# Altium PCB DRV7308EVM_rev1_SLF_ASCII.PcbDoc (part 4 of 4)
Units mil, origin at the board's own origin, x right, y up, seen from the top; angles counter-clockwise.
Board outline 6187 x 6000 mil, 4 copper layers (Top Layer, Ground, Power, Bottom Layer), stack 61.2 mil thick; 306 components, 128 nets, 676 pads, 1026 vias.
Unrouted connection lines stored in the file: 208.
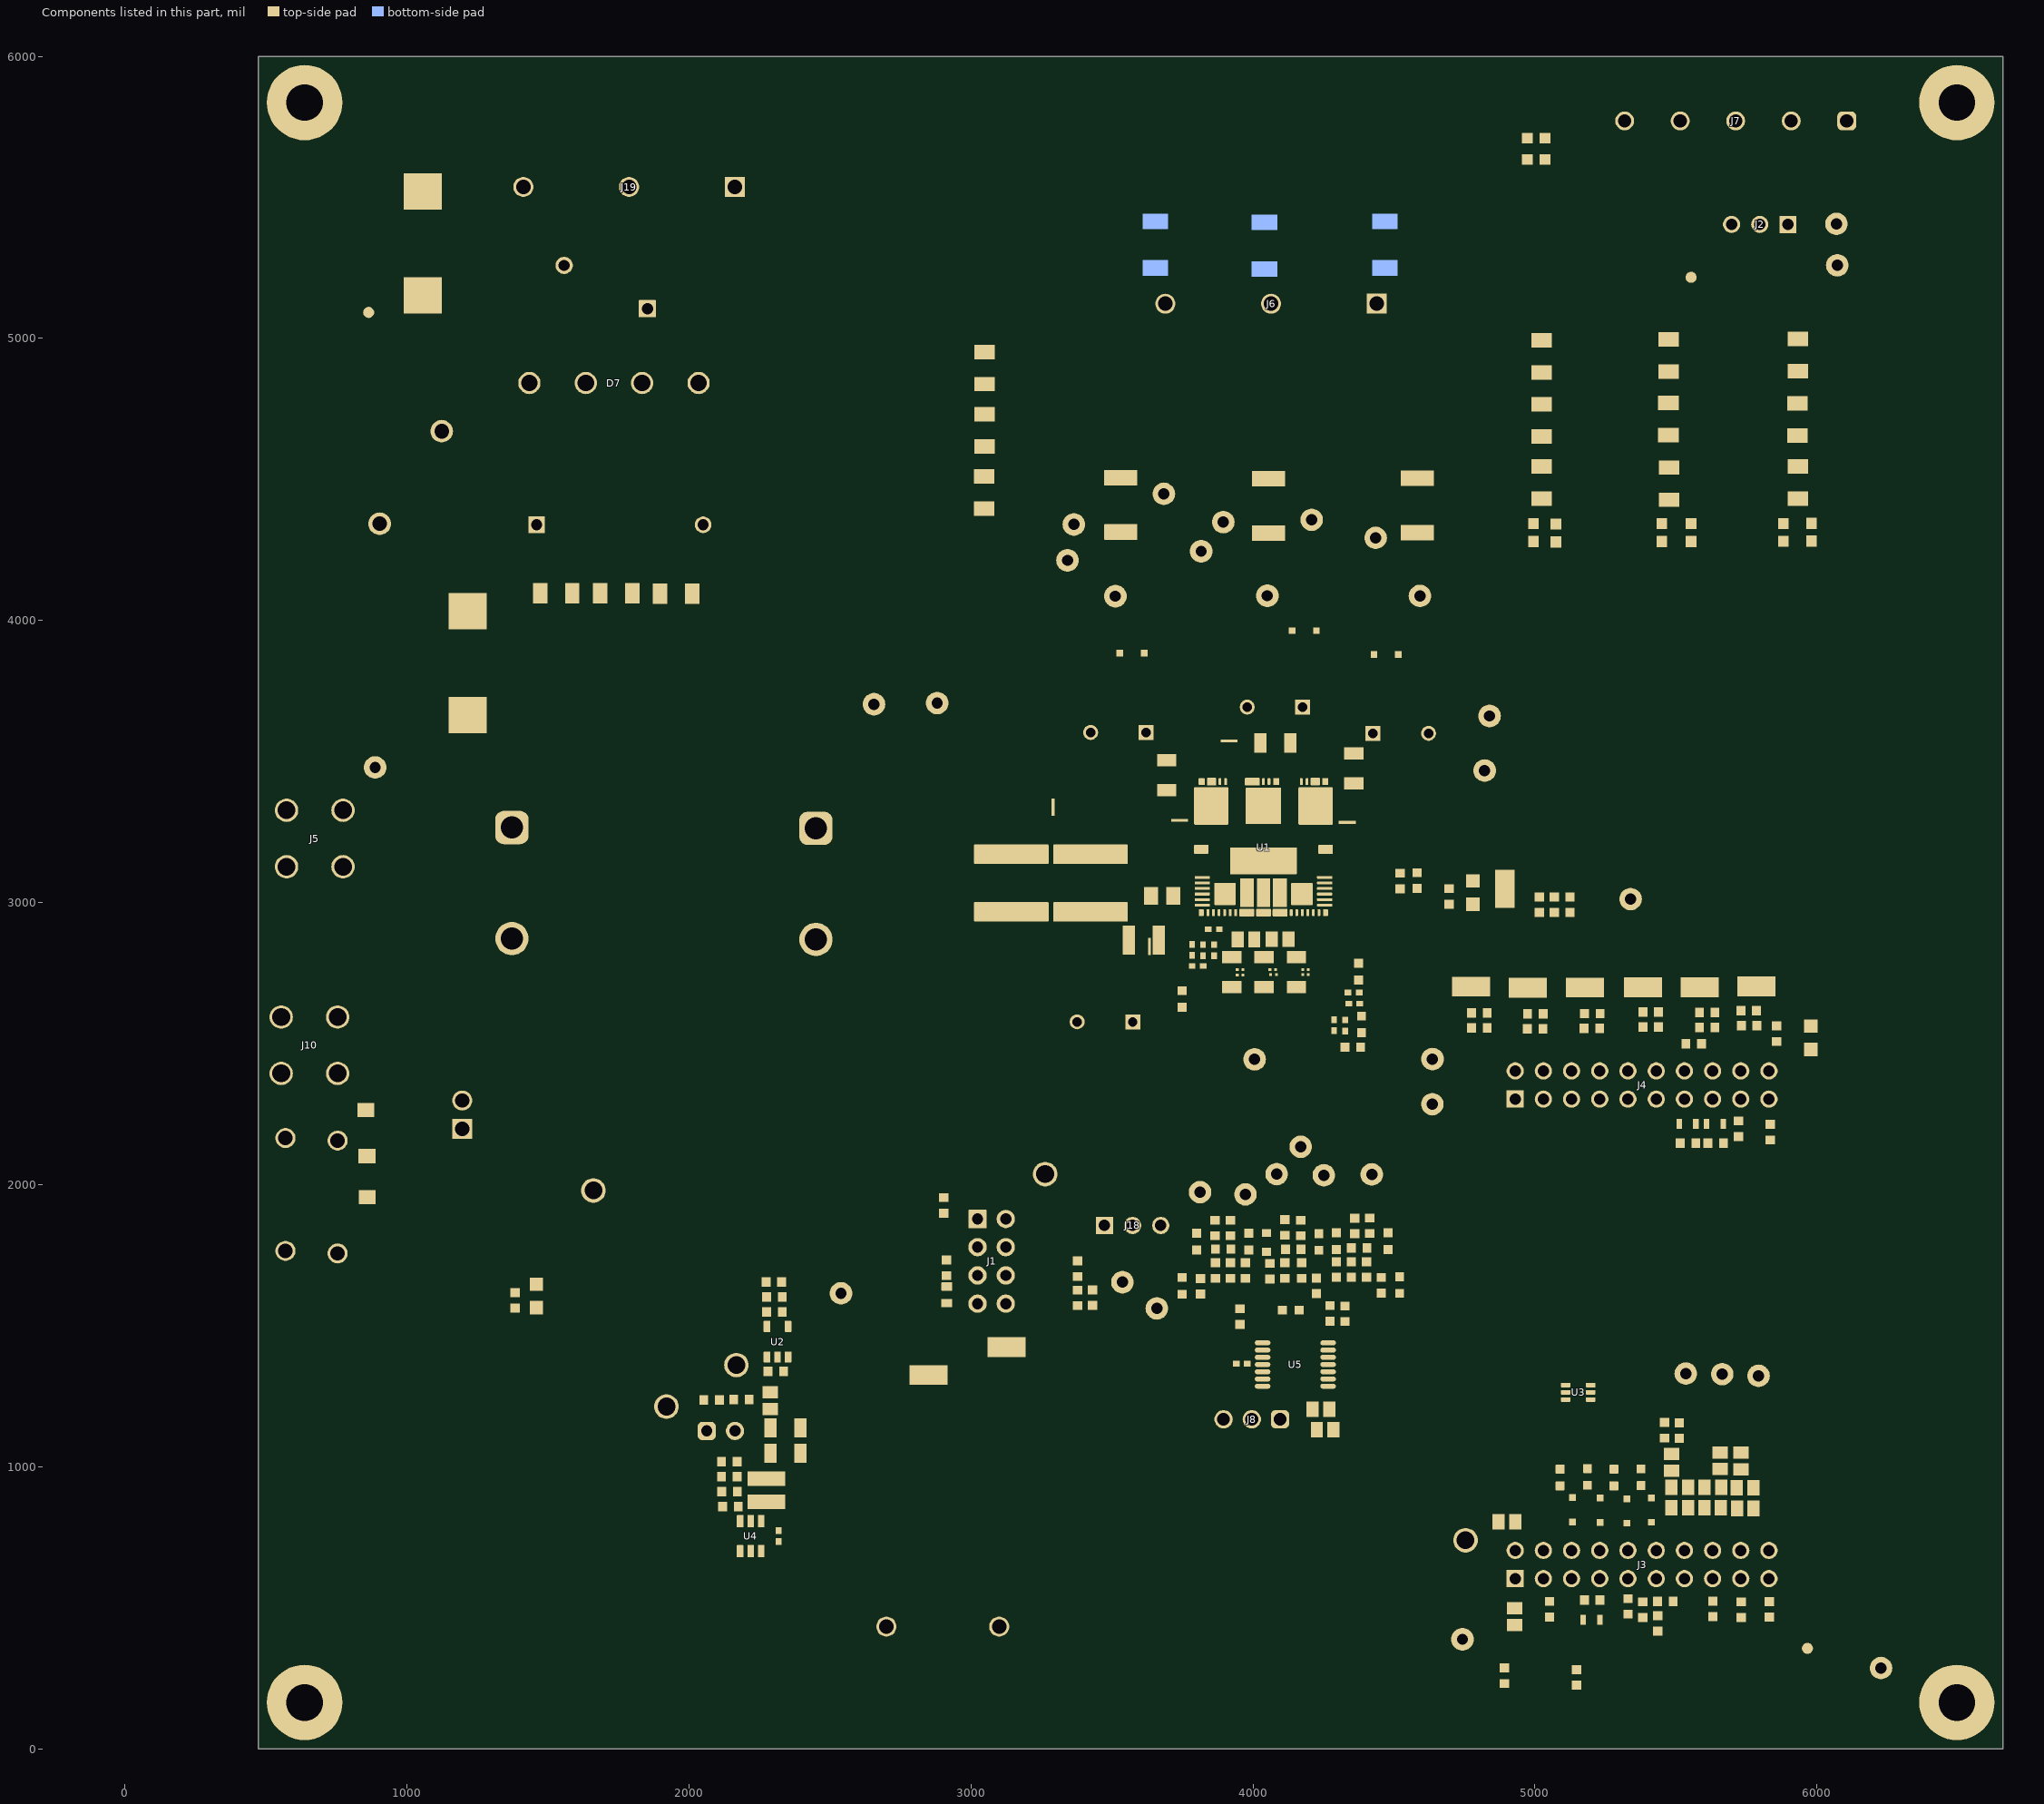
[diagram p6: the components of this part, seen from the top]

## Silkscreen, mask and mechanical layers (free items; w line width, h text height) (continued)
M2 Board Dimensions:
  rectangle: 283.77,-637.3 408.77,-512.3
  rectangle: 408.77,-762.3 783.77,-637.3
  lines w7: 283.77,-637.3 1283.77,-637.3 ; 408.77,-762.3 408.77,-512.3 ; 533.77,-762.3 533.77,-512.3 ; 783.77,-762.3 783.77,-512.3 ; 1033.77,-762.3 1033.77,-512.3 ; 283.77,-762.3 1283.77,-762.3 1283.77,-512.3 283.77,-512.3 283.77,-762.3
  text ".Layer_Name" at 860.77,-1220.79 h35
M3 3D STEP Top:
  text ".Layer_Name" at 860.77,-1220.79 h35
M4 3D STEP Bottom:
  text ".Layer_Name" at 860.77,-1220.79 h35
M5 Assembly Top:
  lines w10: -8.23,-1292.46 6591.77,-1292.46 ; -8.23,-1089.13 6593.77,-1089.13 ; -8.23,-885.8 -8.23,-1495.8 3996.77,-1495.8 6593.77,-1495.8 6593.77,-885.8 -7.73,-885.8 -7.73,-1495.8 1567.77,-1495.8 ; 2456.77,-1495.8 2456.77,-885.8 ; 3723.77,-1089.13 3723.77,-885.8 ; 4563.77,-1089.13 4563.77,-885.8 ; 5185.77,-1502.3 5185.77,-1299.46
  text "COMPONENTS MARKED 'DNP' SHOULD NOT BE POPULATED." at 1437.27,-680.8 h60
  text "ASSEMBLY VARIANT:" at 1436.77,-796.3 h60
  text ".VariantName" at 2472.77,-796.3 h60
  text "PCB VIEWED FROM TOP SIDE" at 55.27,-1017.96 h60
  text "BOARD #:" at 2531.77,-1017.96 h60
  text ".PRJ_Number" at 3077.27,-1017.96 h60
  text "REV:" at 3921.77,-1017.96 h60
  text ".PCB_Rev" at 4213.27,-1017.96 h60
  text "SVN REV:" at 4759.77,-1017.96 h60
  text ".VersionControl_RevNumber" at 5265.77,-1017.96 h60
  text "TID #:" at 2531.77,-1221.3 h60
  text ".TID" at 3077.27,-1221.3 h60
  text "PLOT NAME =" at 55.27,-1426.63 h60
  text ".plot_File_Name" at 860.77,-1426.63 h60
  text "GENERATED    :" at 2533.77,-1426.63 h60
  text ".Print_Date" at 3403.27,-1426.63 h60
  text ".Print_Time" at 4132.27,-1426.63 h60
  text "TEXAS INSTRUMENTS" at 5396.77,-1426.63 h60
M6 Assembly Bottom:
  lines w10: -8.73,-1089.63 6593.27,-1089.63 ; -6.73,-1292.96 6593.27,-1292.96 ; 1399.27,-1502.8 1399.27,-1299.96 ; 2021.27,-1089.63 2021.27,-886.3 ; 2861.27,-1089.63 2861.27,-886.3 ; 4128.27,-1496.3 4128.27,-886.3 ; 5017.27,-1496.3 6592.77,-1496.3 6592.77,-886.3 -8.73,-886.3 -8.73,-1496.3 2588.27,-1496.3 6593.27,-1496.3 6593.27,-886.3
  text "COMPONENTS MARKED 'DNP' SHOULD NOT BE POPULATED." at 6385.77,-680.3 h60
  text ".VariantName" at 5341.77,-796.3 h60
  text "ASSEMBLY VARIANT:" at 6380.77,-796.3 h60
  text ".VersionControl_RevNumber" at 1319.27,-1018.46 h60
  text "SVN REV:" at 1825.27,-1018.46 h60
  text ".PCB_Rev" at 2371.77,-1018.46 h60
  text "REV:" at 2663.27,-1018.46 h60
  text ".PRJ_Number" at 3507.77,-1018.46 h60
  text "BOARD #:" at 4053.27,-1018.46 h60
  text "PCB VIEWED FROM BOTTOM SIDE" at 6529.77,-1018.46 h60
  text ".TID" at 3507.77,-1221.8 h60
  text "TID #:" at 4053.27,-1221.8 h60
  text "TEXAS INSTRUMENTS" at 1188.27,-1427.13 h60
  text ".Print_Time" at 2452.77,-1427.13 h60
  text ".Print_Date" at 3181.77,-1427.13 h60
  text "GENERATED    :" at 4051.27,-1427.13 h60
  text ".plot_File_Name" at 5724.27,-1427.13 h60
  text "PLOT NAME =" at 6529.77,-1427.13 h60
M9 Title Sheet:
  lines w10: -207.73,679.2 -7.73,679.2 ; -207.73,3054.2 -7.73,3054.2 ; -207.73,5429.2 -7.73,5429.2 ; 2292.27,-1695.8 2292.27,-1495.8 ; 2292.27,7604.2 2292.27,7804.2 ; 4792.27,-1695.8 4792.27,-1495.8 ; 4792.27,7604.2 4792.27,7804.2 ; 6604.77,-1495.8 6604.77,-885.8 11587.27,-885.8 ; 7292.27,-1695.8 7292.27,-1495.8 ; 7292.27,7604.2 7292.27,7804.2 ; 9792.27,-1695.8 9792.27,-1495.8 ; 9792.27,7604.2 9792.27,7804.2 ; 11587.27,-1495.8 11587.27,-885.8 ; 11587.27,-1185.8 14587.27,-1185.8 ; 11587.27,-585.8 14587.27,-585.8 ; 11588.27,8.2 14588.27,8.2 ; 12292.27,-1695.8 12292.27,-1495.8 ; 12292.27,7604.2 12292.27,7804.2 ; 13092.27,-1485.8 13092.27,-885.8 ; 14587.27,-885.8 11587.27,-885.8 ; 14587.27,-285.8 11587.27,-285.8 ; 14592.27,-295.8 14592.27,-1495.8 ; 14592.27,508.7 11588.27,508.7 11587.27,508.7 11587.27,8.2 11587.27,-285.8 ; 14592.27,679.2 14792.27,679.2 ; 14592.27,3054.2 14792.27,3054.2 ; 14592.27,5429.2 14792.27,5429.2 ; 11587.27,-885.8 11587.27,-285.8 ; 14592.27,-1495.8 14592.27,7604.2 -7.73,7604.2 -7.73,-1495.8 14592.27,-1495.8 ; -207.73,-1695.8 -207.73,7804.2 14792.27,7804.2 14792.27,-1695.8 -207.73,-1695.8
  text "1" at 1023.61,7674.2 h70
  text "2" at 3519.27,7674.2 h70
  text "3" at 6008.61,7674.2 h70
  text "4" at 8515.28,7674.2 h70
  text "5" at 11014.27,7674.2 h70
  text "6" at 13519.27,7674.2 h70
  text "A" at -132.73,6531.2 h70
  text "A" at 14667.27,6531.2 h70
  text "B" at -132.73,4151.2 h70
  text "B" at 14667.27,4151.2 h70
  text "C" at -132.73,1776.2 h70
  text "C" at 14667.27,1776.2 h70
  text "PROJECT TITLE:" at 11627.27,-84.8 h45
  text ".PRJ_Title" at 11677.27,-218.12 h70
  text "DESIGNED FOR:" at 11627.27,-385.8 h45
  text ".PRJ_Customer" at 11677.27,-525.8 h70
  text "D" at -132.73,-593.8 h70
  text "D" at 14667.27,-593.8 h70
  text "FILE NAME:" at 11627.27,-685.8 h45
  text ".PCB_File_Name_No_Path" at 11677.27,-805.8 h70
  text "Texas Instruments (TI) and/or its licensors do not warrant the accuracy or completeness of this specification" at 6657.77,-967.63 h45
  text "ENGINEER:" at 11627.27,-975.8 h45
  text "LAYOUT BY:" at 13132.27,-975.8 h45
  text "or any information contained therein. TI and/or its licensors do not warrant that this design will meet" at 6612.78,-1080.3 h45
  text ".PRJ_Engineer" at 11677.27,-1130.79 h70
  text ".PCB_Layout" at 13182.77,-1130.79 h70
  text "the specifications, will be suitable for your application or fit for any particular purpose, or will operate in" at 6612.78,-1192.97 h45
  text ".Layer_Name" at 860.77,-1220.79 h60
  text "ALTIUM DESIGNER VERSION:" at 13132.27,-1285.8 h45
  text "an implementation. TI and/or its licensors do not warrant that the design is production worthy. You should" at 6612.78,-1305.63 h45
  text "completely validate and test your design implementation to confirm the system functionality for your application." at 6657.77,-1418.3 h45
  text ".print_Scale" at 11677.27,-1419.12 h70
  text ".Application_BuildNumber" at 13182.77,-1419.12 h70
  text "1" at 1023.61,-1625.8 h70
  text "2" at 3519.27,-1625.8 h70
  text "3" at 6008.61,-1625.8 h70
  text "4" at 8515.28,-1625.8 h70
  text "5" at 11014.27,-1625.8 h70
  text "6" at 13519.27,-1625.8 h70
M10 Fab Notes:
  drawing of 189 lines, arcs and shapes, not listed
  text "DESIGN INFORMATION" at 12665.79,5993.88 h60
  text "MIN. TRACK WIDTH:" at 12021.23,5861.75 h60
  text "8" at 13117.47,5861.75 h60
  text "MIL" at 13272.23,5861.75 h60
  text "MIN. CLEARANCE:" at 12021.23,5737.63 h60
  text "0.2" at 13057.47,5737.63 h60
  text "mm" at 13272.23,5737.63 h60
  text "MIN. VIA PAD SIZE:" at 12021.23,5613.5 h60
  text "24" at 13087.48,5613.5 h60
  text "MIL" at 13272.23,5613.5 h60
  text "0.05mm (2MIL)" at 12716.23,5483.6 h60
  text "MINIMUM ANNULAR RING" at 11692,5475.38 h60
  text "EXTERNAL" at 13424.23,5475.38 h60
  text "PER" at 11892,5365.25 h60
  text "IPC-D-275 CLASS 2 LEVEL C" at 12112,5365.25 h60
  text "MIL, HOLES" at 13600.23,5264.77 h60
  text "+/-" at 13207.77,5256.19 h60
  text "+/-" at 14061.77,5256.19 h60
  text "REGISTRATION TOLERANCES:" at 11692,5255.12 h60
  text "METAL" at 12891.77,5255.12 h60
  text "5" at 13467.97,5255.12 h60
  text "3" at 14300.97,5255.12 h60
  text "MIL" at 14417.23,5255.12 h60
  text "HOLE SIZE TOLERANCE (UNLESS OTHERWISE SPECIFIED):" at 11692,5156.81 h60
  text "+/-" at 14061.77,5153.93 h60
  text "3" at 14300.97,5152.87 h60
  text "MIL" at 14417.23,5152.87 h60
  text "MATERIAL:" at 11617.23,5015.22 h60
  text "FR-4 High Tg" at 12603.67,4886.7 h60
  text "X" at 12459.23,4878.71 h60
  text "FR-408" at 12038.23,4874.19 h60
  text "OTHER" at 13526.23,4874.19 h60
  text "62 MIL (1.6mm) +/-10%" at 12358.33,4731.16 h60
  text "X" at 12238.23,4728.71 h60
  text "THICKNESS:" at 11692,4722.94 h60
  text "OTHER" at 13643.23,4722.94 h60
  text "TOLERANCE:" at 11692,4584.63 h60
  text "X" at 12540.23,4584.63 h60
  text "ANSI IPC-6012 TYPE 3 CLASS 2" at 12718.25,4584.63 h60
  text "OTHER +/-" at 12718.23,4440.44 h60
  text "BOW & TWIST:" at 11692,4295.25 h60
  text "X" at 12540.23,4295.25 h60
  text "ANSI IPC-6012 TYPE 3 CLASS 2" at 12718.25,4295.25 h60
  text "OTHER +/-" at 12718.23,4148.55 h60
  text "DRILLING:" at 11617.23,4017.93 h60
  text "NC_DRILL FILES" at 13378.23,3912.74 h60
  text "REFERENCE:" at 11692,3908.81 h60
  text "X" at 12349.23,3908.71 h60
  text "AS SHOWN" at 12527.23,3908.81 h60
  text "X" at 13250.23,3908.81 h60
  text "OTHER" at 13676.23,3766.55 h60
  text "PTH COPPER THICKNESS:" at 11691.68,3763.03 h60
  text "X" at 12830.91,3763.03 h60
  text "20-30 um" at 12958.91,3763.03 h60
  text "BOARD FINISH:" at 11617.23,3615.43 h60
  text "SILKSCREEN:" at 11772.45,3505.3 h60
  text "X" at 12730.23,3505.3 h60
  text "TOP" at 12847.23,3505.3 h60
  text "X" at 13240.23,3505.3 h60
  text "BOTTOM" at 13358.23,3505.3 h60
  text "SILKSCREEN COLOR:" at 11772.45,3350.11 h60
  text "X" at 12729.23,3350.11 h60
  text "WHITE" at 12847.23,3350.11 h60
  text "OTHER" at 13358.23,3350.11 h60
  text "X" at 12860.23,3206.67 h60
  text "GREEN" at 12978.23,3206.67 h60
  text "OTHER" at 13596.23,3206.67 h60
  text "SOLDER RESIST COLOR:" at 11772.45,3199.8 h60
  text "X" at 12860.23,3052.41 h60
  text "MATTE" at 12978.23,3052.41 h60
  text "SEMI-GLOSS" at 13595.77,3051.78 h60
  text "IMMERSION GOLD (ENIG)" at 12678.23,2879.64 h60
  text "ENEPIG" at 14015.77,2872.42 h60
  text "SURFACE FINISH:" at 11617.23,2871.42 h60
  text "X" at 12500.23,2871.42 h60
  text "IMM. TIN/SILVER OR EQUIV" at 11946.77,2734.11 h60
  text "OTHER" at 13378.23,2730.17 h60
  text "ARRAY/PANEL:" at 11617.23,2574.79 h60
  text "CUT AND TRIM PER M1 BOARD OUTLINE" at 12678.23,2566.57 h60
  text "N.C. ROUTE" at 12678.23,2430.6 h60
  text "X" at 13366.23,2430.6 h60
  text "V. SCORE" at 13544.23,2430.6 h60
  text "CERTIFICATION:" at 11617.23,2301.48 h60
  text "MATERIALS AND WORKMANSHIP FOR ALL PCBS" at 12342.23,2301.48 h60
  text "TO MEET OR EXCEED THE REQUIREMENTS OF:" at 12342.23,2207.41 h60
  text "X" at 11979.74,2078.78 h60
  text "ANSI IPC-A-600F CLASS ->" at 12107.73,2078.78 h60
  text "X" at 13755.74,2078.78 h60
  text "2" at 13865.73,2078.78 h60
  text "1" at 13550.73,2077.29 h60
  text "3" at 14219.73,2077.29 h60
  text "X" at 12791.74,1931.1 h60
  text "RoHS" at 12919.73,1931.1 h60
  text "OTHER" at 13564.13,1931.1 h60
  text "PER ORDER" at 13961.19,1931.1 h60
  text "ALL BOARDS MUST MEET OR EXCEED UL94-V0 REQUIREMENTS." at 11644.77,1777.27 h60
  text "PCB MUST BEAR THE UL94V-0 UL REGISTERED MATERIAL ID NUMBER" at 11644.77,1661.21 h60
  text "ADDITIONAL REQUIREMENTS:" at 11617.23,1491.78 h60
  text "MICROSECTION:" at 11692,1384.66 h60
  text "YES" at 12597.73,1384.66 h60
  text "REQUIRED" at 13459.23,1240.32 h60
  text "BARE BOARD ELEC. TEST:" at 11692,1237.47 h60
  text "NONE" at 12997.73,1237.47 h60
  text "X" at 13341.23,1237.47 h60
  text "PER ORDER" at 14051.23,1237.47 h60
  text "XX MIL VIAS REQUIRE NON-CONDUCTIVE FILL AND PLANARIZE" at 11860.15,1032.52 h59
  text "XX MIL VIAS REQUIRE CONDUCTIVE FILL AND PLANARIZE" at 11868.15,928.55 h60
  text "OUTER XX MIL TRACES REQUIRE 50 OHM SINGLE-ENDED IMPEDANCE" at 11867.16,765.16 h58
  text "LAYER 2 & 3 (INNER LAYERS) XX MIL WIDE, XX MIL SPACE / TRACES REQUIRE 100 OHM DIFFERENTIAL IMPEDANCE" at 11859.16,529.45 h60
  text ".Layer_Name" at 860.77,-1220.79 h60
M11 Gerber Information:
  lines w10: -8.23,-1292.46 6591.77,-1292.46 ; -8.23,-1089.13 6593.77,-1089.13 ; -8.23,-885.8 -8.23,-1495.8 3996.77,-1495.8 6593.77,-1495.8 6593.77,-885.8 -7.73,-885.8 -7.73,-1495.8 1567.77,-1495.8 ; 2456.77,-1495.8 2456.77,-885.8 ; 3723.77,-1089.13 3723.77,-885.8 ; 4563.77,-1089.13 4563.77,-885.8 ; 5185.77,-1502.3 5185.77,-1299.46
  text "ALL ARTWORK VIEWED FROM TOP SIDE" at 55.27,-1017.96 h60
  text "BOARD #:" at 2531.77,-1017.96 h60
  text ".PRJ_Number" at 3077.27,-1017.96 h60
  text "REV:" at 3921.77,-1017.96 h60
  text ".PCB_Rev" at 4213.27,-1017.96 h60
  text "SVN REV:" at 4759.77,-1017.96 h60
  text ".VersionControl_RevNumber" at 5265.77,-1017.96 h60
  text "LAYER NAME =" at 55.27,-1220.79 h60
  text "TID #:" at 2531.77,-1221.3 h60
  text ".TID" at 3077.27,-1221.3 h60
  text "PLOT NAME =" at 55.27,-1426.63 h60
  text ".plot_File_Name" at 860.77,-1426.63 h60
  text "GENERATED    :" at 2533.77,-1426.63 h60
  text ".Print_Date" at 3403.27,-1426.63 h60
  text ".Print_Time" at 4132.27,-1426.63 h60
  text "TEXAS INSTRUMENTS" at 5396.77,-1426.63 h60
M12 Stackup:
  drawing of 295 lines, arcs and shapes, not listed
  text ".Layer_Name" at 860.77,-1220.79 h60
  text "Layer" at 15606.58,-1911 h60
  text "Name" at 16016.49,-1911 h60
  text "Material" at 16946.23,-1911 h60
  text "Thickness" at 17806,-1911 h60
  text "Constant" at 18455.84,-1911 h60
  text "Board Layer Stack" at 19025.7,-1911 h60
  text "Top Overlay" at 16016.49,-2031 h60
  text "Top Solder" at 16016.49,-2151 h60
  text "Solder Resist" at 16946.23,-2151 h60
  text "0.40mil" at 17806,-2151 h60
  text "3.5" at 18455.84,-2151 h60
  text "1" at 15606.58,-2271 h60
  text "Top Layer" at 16016.49,-2271 h60
  text "4.20mil" at 17806,-2271 h60
  text "Dielectric 1" at 16016.49,-2391 h60
  text "FR-4 High Tg" at 16946.23,-2391 h60
  text "8.00mil" at 17806,-2391 h60
  text "4.2" at 18455.84,-2391 h60
  text "2" at 15606.58,-2511 h60
  text "Ground" at 16016.49,-2511 h60
  text "1.40mil" at 17806,-2511 h60
  text "Dielectric 2" at 16016.49,-2631 h60
  text "FR-4 High Tg" at 16946.23,-2631 h60
  text "34.00mil" at 17806,-2631 h60
  text "4.2" at 18455.84,-2631 h60
  text "3" at 15606.58,-2751 h60
  text "Power" at 16016.49,-2751 h60
  text "1.40mil" at 17806,-2751 h60
  text "Dielectric 3" at 16016.49,-2871 h60
  text "FR-4 High Tg" at 16946.23,-2871 h60
  text "8.00mil" at 17806,-2871 h60
  text "4.2" at 18455.84,-2871 h60
  text "4" at 15606.58,-2991 h60
  text "Bottom Layer" at 16016.49,-2991 h60
  text "4.20mil" at 17806,-2991 h60
  text "Bottom Solder" at 16016.49,-3111 h60
  text "Solder Resist" at 16946.23,-3111 h60
  text "0.40mil" at 17806,-3111 h60
  text "3.5" at 18455.84,-3111 h60
  text "Bottom Overlay" at 16016.49,-3231 h60
M13 Component Bodies Top:
  text ".Layer_Name" at 860.77,-1220.79 h60
M14 Component Bodies Bottom:
  text ".Layer_Name" at 860.77,-1220.79 h60
M15 Courtyards Top:
  text ".Layer_Name" at 860.77,-1220.79 h60
M16 Courtyards Bottom:
  text ".Layer_Name" at 860.77,-1220.79 h60
Drill Drawing:
  circle w10: c5647.49,3109.96 r16.58
  circle w10: c5647.49,3109.96 r27.63
  circle w10: c5647.49,2985.64 r27.63
  lines w10: 5619.86,1770.07 5675.11,1770.07 5647.49,1714.81 5619.86,1770.07 ; 5619.86,1977.27 5633.67,1977.27 5633.67,1963.45 5661.3,1963.45 5661.3,1977.27 5675.11,1977.27 5675.11,2004.89 5661.3,2004.89 5661.3,2018.71 5633.67,2018.71 5633.67,2004.89 5619.86,2004.89 5619.86,1977.27 ; 5619.86,2087.77 5675.11,2087.77 5675.11,2143.03 5619.86,2143.03 5619.86,2087.77 ; 5619.86,2225.91 5633.67,2225.91 5633.67,2212.09 5661.3,2212.09 5661.3,2225.91 5675.11,2225.91 5675.11,2253.53 5661.3,2253.53 5661.3,2267.35 5633.67,2267.35 5633.67,2253.53 5619.86,2253.53 5619.86,2225.91 ; 5619.86,2391.67 5675.11,2391.67 5647.49,2336.41 5619.86,2391.67 ; 5619.86,2460.73 5619.86,2474.55 5633.67,2488.36 5619.86,2502.17 5619.86,2515.99 5633.67,2515.99 5647.49,2502.17 5661.3,2515.99 5675.11,2515.99 5675.11,2502.17 5661.3,2488.36 5675.11,2474.55 5675.11,2460.73 5661.3,2460.73 5647.49,2474.55 5633.67,2460.73 5619.86,2460.73 ; 5619.86,2585.05 5647.49,2598.87 5675.11,2585.05 5661.3,2612.68 5675.11,2640.31 5647.49,2626.49 5619.86,2640.31 5633.67,2612.68 5619.86,2585.05 ; 5619.86,2709.37 5647.49,2723.19 5675.11,2709.37 5661.3,2737 5675.11,2764.63 5647.49,2750.81 5619.86,2764.63 5633.67,2737 5619.86,2709.37 ; 5619.86,2847.51 5633.67,2847.51 5647.49,2833.69 5661.3,2847.51 5675.11,2847.51 5661.3,2861.32 5675.11,2875.13 5661.3,2875.13 5647.49,2888.95 5633.67,2875.13 5619.86,2875.13 5633.67,2861.32 5619.86,2847.51 ; 5619.86,3206.65 5675.11,3206.65 5675.11,3261.91 5619.86,3261.91 5619.86,3206.65 ; 5619.86,3482.92 5647.49,3455.29 5675.11,3482.92 5647.49,3510.55 5619.86,3482.92 ; 5630.91,1759.02 5664.06,1759.02 5647.49,1725.86 5630.91,1759.02 ; 5630.91,2098.82 5664.06,2098.82 5664.06,2131.98 5630.91,2131.98 5630.91,2098.82 ; 5630.91,2231.43 5639.2,2231.43 5639.2,2223.14 5655.77,2223.14 5655.77,2231.43 5664.06,2231.43 5664.06,2248.01 5655.77,2248.01 5655.77,2256.3 5639.2,2256.3 5639.2,2248.01 5630.91,2248.01 5630.91,2231.43 ; 5630.91,2720.42 5647.49,2728.71 5664.06,2720.42 5655.77,2737 5664.06,2753.58 5647.49,2745.29 5630.91,2753.58 5639.2,2737 5630.91,2720.42 ; 5630.91,2853.03 5639.2,2853.03 5647.49,2844.74 5655.77,2853.03 5664.06,2853.03 5655.77,2861.32 5664.06,2869.61 5655.77,2869.61 5647.49,2877.9 5639.2,2869.61 5630.91,2869.61 5639.2,2861.32 5630.91,2853.03
  lines w12: 5569.77,1553.2 8801.26,1553.2 ; 5569.77,3666.64 8801.26,3666.64 ; 5907.63,1428.88 5907.63,3790.96 ; 6239.63,1428.88 6239.63,3790.96 ; 6876.2,1428.88 6876.2,3790.96 ; 7135.34,1428.88 7135.34,3790.96 ; 7510.49,1428.88 7510.49,3790.96 ; 8234.82,1428.88 8234.82,3790.96 ; 5569.77,1428.88 8801.26,1428.88 8801.26,3790.96 5569.77,3790.96 5569.77,1428.88
  text "Symbol" at 5644.36,3703.93 h72
  text "Quantity" at 5944.93,3703.93 h72
  text "Finished Hole Size" at 6276.93,3703.93 h72
  text "Plated" at 6913.49,3703.93 h72
  text "Hole Type" at 7172.63,3703.93 h72
  text "Drill Layer Pair" at 7547.79,3703.93 h72
  text "Hole Tolerance" at 8272.12,3703.93 h72
  text "57" at 5944.93,3579.61 h60
  text "7.87mil (0.200mm)" at 6276.93,3579.61 h60
  text "PTH" at 6913.49,3579.61 h60
  text "Round" at 7172.63,3579.61 h60
  text "Top Layer - Bottom Layer" at 7547.79,3579.61 h60
  text "B" at 5619.08,3569.62 h55.25
  text "945" at 5944.93,3455.29 h60
  text "10.00mil (0.254mm)" at 6276.93,3455.29 h60
  text "PTH" at 6913.49,3455.29 h60
  text "Round" at 7172.63,3455.29 h60
  text "Top Layer - Bottom Layer" at 7547.79,3455.29 h60
  text "24" at 5944.93,3330.97 h60
  text "19.69mil (0.500mm)" at 6276.93,3330.97 h60
  text "PTH" at 6913.49,3330.97 h60
  text "Round" at 7172.63,3330.97 h60
  text "Top Layer - Bottom Layer" at 7547.79,3330.97 h60
  text "E" at 5619.08,3320.98 h55.25
  text "8" at 5944.93,3206.65 h60
  text "33.47mil (0.850mm)" at 6276.93,3206.65 h60
  text "PTH" at 6913.49,3206.65 h60
  text "Round" at 7172.63,3206.65 h60
  text "Top Layer - Bottom Layer" at 7547.79,3206.65 h60
  text "4" at 5944.93,3082.33 h60
  text "39.37mil (1.000mm)" at 6276.93,3082.33 h60
  text "PTH" at 6913.49,3082.33 h60
  text "Round" at 7172.63,3082.33 h60
  text "Top Layer - Bottom Layer" at 7547.79,3082.33 h60
  text "45" at 5944.93,2958.01 h60
  text "40.00mil (1.016mm)" at 6276.93,2958.01 h60
  text "PTH" at 6913.49,2958.01 h60
  text "Round" at 7172.63,2958.01 h60
  text "Top Layer - Bottom Layer" at 7547.79,2958.01 h60
  text "46" at 5944.93,2833.69 h60
  text "40.16mil (1.020mm)" at 6276.93,2833.69 h60
  text "PTH" at 6913.49,2833.69 h60
  text "Round" at 7172.63,2833.69 h60
  text "Top Layer - Bottom Layer" at 7547.79,2833.69 h60
  text "3" at 5944.93,2709.37 h60
  text "45.28mil (1.150mm)" at 6276.93,2709.37 h60
  text "PTH" at 6913.49,2709.37 h60
  text "Round" at 7172.63,2709.37 h60
  text "Top Layer - Bottom Layer" at 7547.79,2709.37 h60
  text "5" at 5944.93,2585.05 h60
  text "47.24mil (1.200mm)" at 6276.93,2585.05 h60
  text "PTH" at 6913.49,2585.05 h60
  text "Round" at 7172.63,2585.05 h60
  text "Top Layer - Bottom Layer" at 7547.79,2585.05 h60
  text "6" at 5944.93,2460.73 h60
  text "51.18mil (1.300mm)" at 6276.93,2460.73 h60
  text "PTH" at 6913.49,2460.73 h60
  text "Round" at 7172.63,2460.73 h60
  text "Top Layer - Bottom Layer" at 7547.79,2460.73 h60
  text "+/-3.94mil" at 8272.12,2460.73 h60
  text "8" at 5944.93,2336.41 h60
  text "51.18mil (1.300mm)" at 6276.93,2336.41 h60
  text "PTH" at 6913.49,2336.41 h60
  text "Round" at 7172.63,2336.41 h60
  text "Top Layer - Bottom Layer" at 7547.79,2336.41 h60
  text "2" at 5944.93,2212.09 h60
  text "52.00mil (1.321mm)" at 6276.93,2212.09 h60
  text "PTH" at 6913.49,2212.09 h60
  text "Round" at 7172.63,2212.09 h60
  text "Top Layer - Bottom Layer" at 7547.79,2212.09 h60
  text "4" at 5944.93,2087.77 h60
  text "59.06mil (1.500mm)" at 6276.93,2087.77 h60
  text "PTH" at 6913.49,2087.77 h60
  text "Round" at 7172.63,2087.77 h60
  text "Top Layer - Bottom Layer" at 7547.79,2087.77 h60
  text "8" at 5944.93,1963.45 h60
  text "62.99mil (1.600mm)" at 6276.93,1963.45 h60
  text "PTH" at 6913.49,1963.45 h60
  text "Round" at 7172.63,1963.45 h60
  text "Top Layer - Bottom Layer" at 7547.79,1963.45 h60
  text "+3.94mil/-0.00mil" at 8272.12,1963.45 h60
  text "5" at 5944.93,1839.13 h60
  text "63.00mil (1.600mm)" at 6276.93,1839.13 h60
  text "PTH" at 6913.49,1839.13 h60
  text "Round" at 7172.63,1839.13 h60
  text "Top Layer - Bottom Layer" at 7547.79,1839.13 h60
  text "F" at 5619.08,1829.14 h55.25
  text "4" at 5944.93,1714.81 h60
  text "78.74mil (2.000mm)" at 6276.93,1714.81 h60
  text "PTH" at 6913.49,1714.81 h60
  text "Round" at 7172.63,1714.81 h60
  text "Top Layer - Bottom Layer" at 7547.79,1714.81 h60
  text "+/-3.94mil" at 8272.12,1714.81 h60
  text "4" at 5944.93,1590.49 h60
  text "129.92mil (3.300mm)" at 6276.93,1590.49 h60
  text "PTH" at 6913.49,1590.49 h60
  text "Round" at 7172.63,1590.49 h60
  text "Top Layer - Bottom Layer" at 7547.79,1590.49 h60
  text "D" at 5619.08,1580.5 h55.25
  text "1178 Total" at 5944.93,1466.17 h60
  text ".Layer_Name" at 860.77,-1220.79 h60
Mechanical 17:
  text ".Layer_Name" at 860.77,-1220.79 h60
Mechanical 18:
  text ".Layer_Name" at 860.77,-1220.79 h60
Mechanical 19:
  text ".Layer_Name" at 860.77,-1220.79 h60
